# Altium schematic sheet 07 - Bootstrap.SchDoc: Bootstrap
size A3; PageSetup: Record=PageOptions¦CenterHorizontal=True¦CenterVertical=True¦PrintScale=0.70¦XCorrection=1.00¦YCorrection=1.00¦PrintKind=0¦BorderSize=5000000¦LeftOffset=0¦BottomOffset=0¦Orientation=2¦PaperLength=4200¦PaperWidth=2970¦Scale=100¦PaperSource=7¦PrintQuality=600¦MediaType=1¦DitherType=10¦PaperKind=A4¦PrintScaleMode=1; Author: Juan Anzola; SheetNumber: 7; SheetTotal: 21
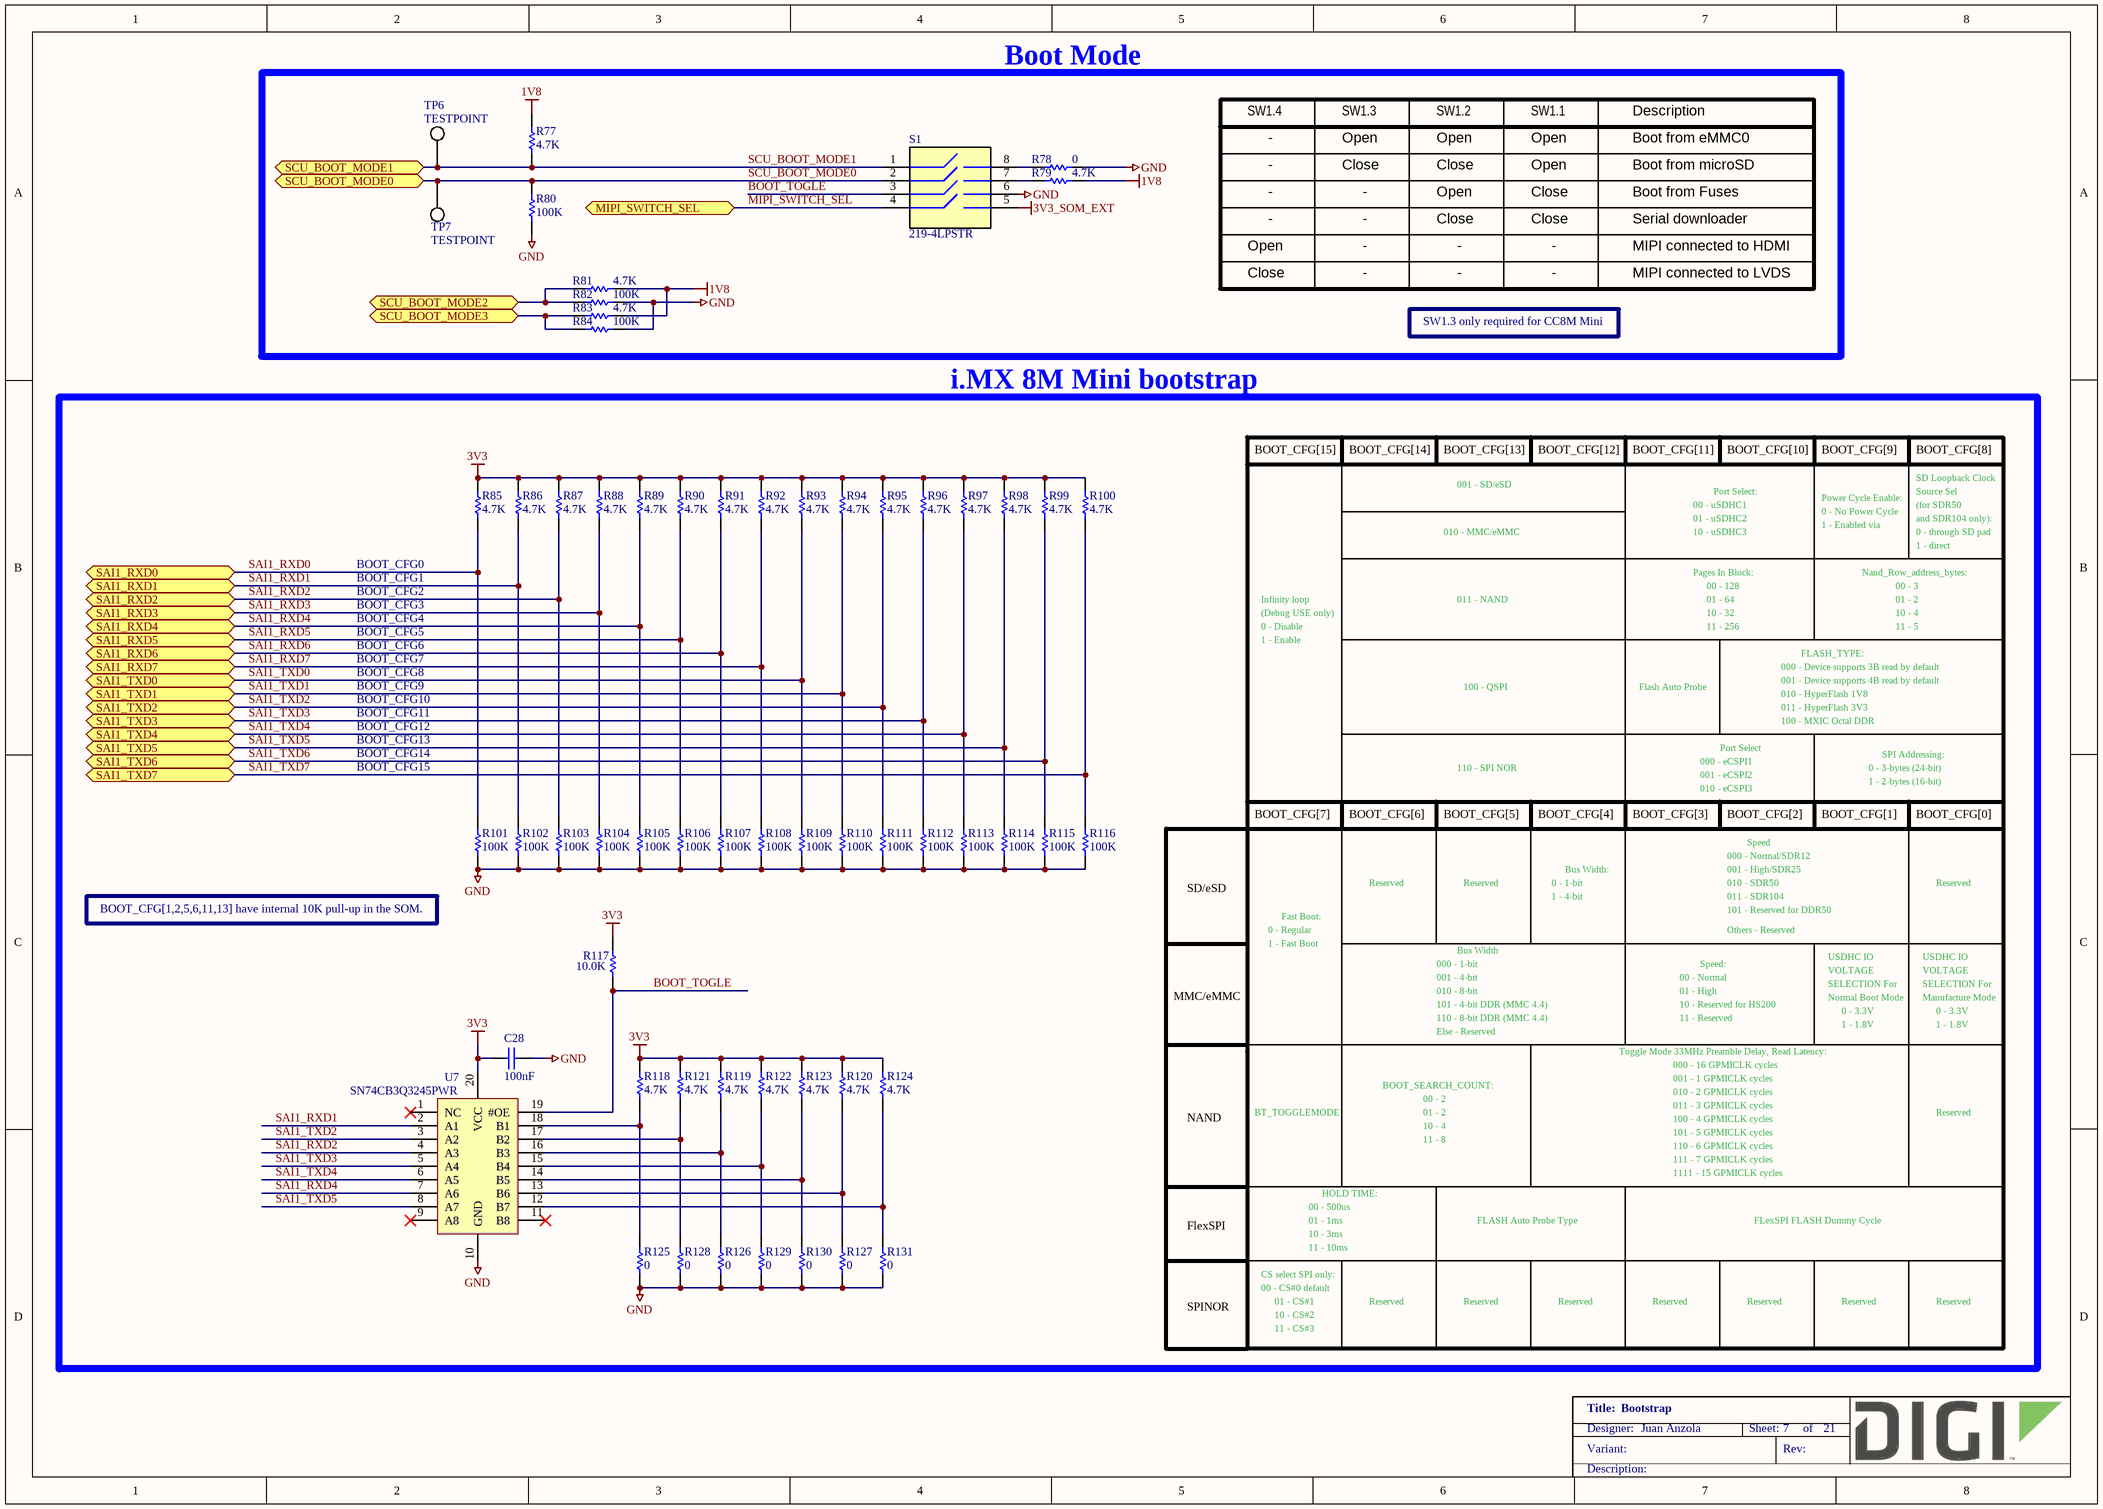
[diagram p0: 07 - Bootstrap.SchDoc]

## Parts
C28  100nF  [CAPC1005X55N]
R77  4.7K  [RESC1005X40N]
R78  0  [RESC1005X40N]
R79  4.7K  [RESC1005X40N]
R80  100K  [RESC1005X40N]
R81  4.7K  [RESC1005X40N]
R82  100K  [RESC1005X40N]
R83  4.7K  [RESC1005X40N]
R84  100K  [RESC1005X40N]
R85  4.7K  [RESC1005X40N]
R86  4.7K  [RESC1005X40N]
R87  4.7K  [RESC1005X40N]
R88  4.7K  [RESC1005X40N]
R89  4.7K  [RESC1005X40N]
R90  4.7K  [RESC1005X40N]
R91  4.7K  [RESC1005X40N]
R92  4.7K  [RESC1005X40N]
R93  4.7K  [RESC1005X40N]
R94  4.7K  [RESC1005X40N]
R95  4.7K  [RESC1005X40N]
R96  4.7K  [RESC1005X40N]
R97  4.7K  [RESC1005X40N]
R98  4.7K  [RESC1005X40N]
R99  4.7K  [RESC1005X40N]
R100  4.7K  [RESC1005X40N]
R101  100K  [RESC1005X40N]
R102  100K  [RESC1005X40N]
R103  100K  [RESC1005X40N]
R104  100K  [RESC1005X40N]
R105  100K  [RESC1005X40N]
R106  100K  [RESC1005X40N]
R107  100K  [RESC1005X40N]
R108  100K  [RESC1005X40N]
R109  100K  [RESC1005X40N]
R110  100K  [RESC1005X40N]
R111  100K  [RESC1005X40N]
R112  100K  [RESC1005X40N]
R113  100K  [RESC1005X40N]
R114  100K  [RESC1005X40N]
R115  100K  [RESC1005X40N]
R116  100K  [RESC1005X40N]
R117  10.0K  [RESC1005X40N]
R118  4.7K  [RESC1005X40N]
R119  4.7K  [RESC1005X40N]
R120  4.7K  [RESC1005X40N]
R121  4.7K  [RESC1005X40N]
R122  4.7K  [RESC1005X40N]
R123  4.7K  [RESC1005X40N]
R124  4.7K  [RESC1005X40N]
R125  0  [RESC1005X40N]
R126  0  [RESC1005X40N]
R127  0  [RESC1005X40N]
R128  0  [RESC1005X40N]
R129  0  [RESC1005X40N]
R130  0  [RESC1005X40N]
R131  0  [RESC1005X40N]
S1  219-4LPSTR  [SOIC254P991X420-8N]
TP6  TESTPOINT  [TP0762]  (no BOM)
TP7  TESTPOINT  [TP0762]  (no BOM)
U7  SN74CB3Q3245PWR  [SOP65P640X120-20N]

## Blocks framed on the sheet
Boot Mode: R77-R84 S1 TP6 TP7
i.MX 8M Mini bootstrap: C28 R85-R131 U7

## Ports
MIPI_SWITCH_SEL (bidir), SAI1_RXD0 (bidir), SAI1_RXD1 (bidir), SAI1_RXD2 (bidir), SAI1_RXD3 (bidir), SAI1_RXD4 (bidir), SAI1_RXD5 (bidir), SAI1_RXD6 (bidir), SAI1_RXD7 (bidir), SAI1_TXD0 (bidir), SAI1_TXD1 (bidir), SAI1_TXD2 (bidir), SAI1_TXD3 (bidir), SAI1_TXD4 (bidir), SAI1_TXD5 (bidir), SAI1_TXD6 (bidir), SAI1_TXD7 (bidir), SCU_BOOT_MODE0 (bidir), SCU_BOOT_MODE1 (bidir), SCU_BOOT_MODE2 (bidir), SCU_BOOT_MODE3 (bidir)

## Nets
1V8: R77.2 R79.2 R81.1 R83.1
3V3: C28.2 R85.1 R86.1 R87.1 R88.1 R89.1 R90.1 R91.1 R92.1 R93.1 R94.1 R95.1 R96.1 R97.1 R98.1 R99.1 R100.1 R117.1 R118.1 R119.1 R120.1 R121.1 R122.1 R123.1 R124.1 U7.20(VCC)
3V3_SOM_EXT: S1.5
GND: C28.1 R78.2 R80.1 R82.1 R84.1 R101.2 R102.2 R103.2 R104.2 R105.2 R106.2 R107.2 R108.2 R109.2 R110.2 R111.2 R112.2 R113.2 R114.2 R115.2 R116.2 R125.1 R126.1 R127.1 R128.1 R129.1 R130.1 R131.1 S1.6 U7.10(GND)
BOOT_TOGLE: R117.2 S1.3 U7.19(#OE)
MIPI_SWITCH_SEL: S1.4 ; port MIPI_SWITCH_SEL
SAI1_RXD0: R85.2 R101.1 ; port SAI1_RXD0
SAI1_RXD1: R86.2 R102.1 U7.2(A1) ; port SAI1_RXD1
SAI1_RXD2: R87.2 R103.1 U7.4(A3) ; port SAI1_RXD2
SAI1_RXD3: R88.2 R104.1 ; port SAI1_RXD3
SAI1_RXD4: R89.2 R105.1 U7.7(A6) ; port SAI1_RXD4
SAI1_RXD5: R90.2 R106.1 ; port SAI1_RXD5
SAI1_RXD6: R91.2 R107.1 ; port SAI1_RXD6
SAI1_RXD7: R92.2 R108.1 ; port SAI1_RXD7
SAI1_TXD0: R93.2 R109.1 ; port SAI1_TXD0
SAI1_TXD1: R94.2 R110.1 ; port SAI1_TXD1
SAI1_TXD2: R95.2 R111.1 U7.3(A2) ; port SAI1_TXD2
SAI1_TXD3: R96.2 R112.1 U7.5(A4) ; port SAI1_TXD3
SAI1_TXD4: R97.2 R113.1 U7.6(A5) ; port SAI1_TXD4
SAI1_TXD5: R98.2 R114.1 U7.8(A7) ; port SAI1_TXD5
SAI1_TXD6: R99.2 R115.1 ; port SAI1_TXD6
SAI1_TXD7: R100.2 R116.1 ; port SAI1_TXD7
SCU_BOOT_MODE0: R80.2 S1.2 TP7.1 ; port SCU_BOOT_MODE0
SCU_BOOT_MODE1: R77.1 S1.1 TP6.1 ; port SCU_BOOT_MODE1
SCU_BOOT_MODE2: R81.2 R82.2 ; port SCU_BOOT_MODE2
SCU_BOOT_MODE3: R83.2 R84.2 ; port SCU_BOOT_MODE3
NetR78_1: R78.1 S1.8
NetR79_1: R79.1 S1.7
NetR118_2: R118.2 R125.2 U7.18(B1)
NetR119_2: R119.2 R126.2 U7.16(B3)
NetR120_2: R120.2 R127.2 U7.13(B6)
NetR121_2: R121.2 R128.2 U7.17(B2)
NetR122_2: R122.2 R129.2 U7.15(B4)
NetR123_2: R123.2 R130.2 U7.14(B5)
NetR124_2: R124.2 R131.2 U7.12(B7)

Not connected (* = marked no-connect by the designer): U7 1(NC)* 9(A8)* 11(B8)*

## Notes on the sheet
- SW1.4
- -
- SW1.3
- Open
- Close
- SW1.2
- SW1.1
- Description
- Boot from eMMC0
- Boot from microSD
- Boot from Fuses
- Serial downloader
- MIPI connected to HDMI
- MIPI connected to LVDS
- SW1.3 only required for CC8M Mini
- BOOT_CFG[15]
- BOOT_CFG[14]
- BOOT_CFG[13]
- BOOT_CFG[12]
- BOOT_CFG[11]
- BOOT_CFG[10]
- BOOT_CFG[9]
- BOOT_CFG[8]
- 001 - SD/eSD
- 00 - uSDHC1
- Port Select:
- Power Cycle Enable:
- 0 - No Power Cycle
- SD Loopback Clock
- Source Sel
- (for SDR50
- BOOT_CFG0
- BOOT_CFG1
- 010 - MMC/eMMC
- 01 - uSDHC2
- 10 - uSDHC3
- Pages In Block:
- 00 - 128
- 1 - Enabled via
- Nand_Row_address_bytes:
- 00 - 3
- and SDR104 only):
- 0 - through SD pad
- 1 - direct
- BOOT_CFG2
- BOOT_CFG3
- BOOT_CFG4
- BOOT_CFG5
- BOOT_CFG6
- Infinity loop
- (Debug USE only)
- 0 - Disable
- 1 - Enable
- 011 - NAND
- 01 - 64
- 10 - 32
- 11 - 256
- 01 - 2
- 11 - 5
- 10 - 4
- BOOT_CFG7
- BOOT_CFG8
- BOOT_CFG9
- BOOT_CFG11
- BOOT_CFG10
- 100 - QSPI
- Flash Auto Probe
- 000 - Device supports 3B read by default
- 001 - Device supports 4B read by default
- 010 - HyperFlash 1V8
- 100 - MXIC Octal DDR
- 011 - HyperFlash 3V3
- FLASH_TYPE:
- BOOT_CFG12
- BOOT_CFG13
- BOOT_CFG14
- BOOT_CFG15
- 110 - SPI NOR
- 000 - eCSPI1
- 001 - eCSPI2
- Port Select
- 0 - 3-bytes (24-bit)
- 1 - 2-bytes (16-bit)
- SPI Addressing:
- BOOT_CFG[7]
- BOOT_CFG[6]
- BOOT_CFG[5]
- BOOT_CFG[4]
- BOOT_CFG[3]
- 010 - eCSPI3
- BOOT_CFG[2]
- 000 - Normal/SDR12
- Speed
- BOOT_CFG[1]
- BOOT_CFG[0]
- BOOT_CFG[1,2,5,6,11,13] have internal 10K pull-up in the SOM.
- SD/eSD
- Fast Boot:
- Reserved
- 0 - 1-bit
- 1 - 4-bit
- Bus Width:
- 001 - High/SDR25
- 010 - SDR50
- 011 - SDR104
- 101 - Reserved for DDR50
- 0 - Regular
- 1 - Fast Boot
- 000 - 1-bit
- 001 - 4-bit
- 010 - 8-bit
- Bus Width
- 00 - Normal
- 01 - High
- Speed:
- Others - Reserved
- USDHC IO
- SELECTION For
- VOLTAGE
- MMC/eMMC
- 101 - 4-bit DDR (MMC 4.4)
- 110 - 8-bit DDR (MMC 4.4)
- Else - Reserved
- Toggle Mode 33MHz Preamble Delay, Read Latency:
- 10 - Reserved for HS200
- 11 - Reserved
- Normal Boot Mode
- 0 - 3.3V
- 1 - 1.8V
- Manufacture Mode
- NAND
- BT_TOGGLEMODE
- BOOT_SEARCH_COUNT:
- 00 - 2
- 000 - 16 GPMICLK cycles
- 001 - 1 GPMICLK cycles
- 010 - 2 GPMICLK cycles
- 011 - 3 GPMICLK cycles
- 100 - 4 GPMICLK cycles
- 11 - 8
- 101 - 5 GPMICLK cycles
- 110 - 6 GPMICLK cycles
- 111 - 7 GPMICLK cycles
- 1111 - 15 GPMICLK cycles
- FlexSPI
- 00 - 500us
- 01 - 1ms
- 10 - 3ms
- 11 - 10ms
- HOLD TIME:
- FLASH Auto Probe Type
- FLexSPI FLASH Dummy Cycle
- SPINOR
- CS select SPI only:
- 00 - CS#0 default
- 01 - CS#1
- 10 - CS#2
- 11 - CS#3

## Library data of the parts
C28 = 1000006: CAP 100nF 16V 10% X7R 0402; Part_Type: Capacitor; Manufacturer: Murata; Manufacturer_Part_Number: GRM155R71C104KA88D; Component_Life_Cycle_State: CAD Reviewed; Area: 0.95; Project: KITT; Tolerance: 10; Digi_PN: 14050552
R77 R79 R81 R83 R85-R100 R118-R124 = 1000038: RES 4.7K OHM 1/10W 5% 0402 SMD; Part_Type: Resistor; Manufacturer: Panasonic - ECG; Manufacturer_Part_Number: ERJ-2GEJ472X; Digi_PN: 13050549; Component_Life_Cycle_State: Proven; Area: 0,95; Project: Adjustable Foundation; Power_WV_SRF: 100; Tolerance: 5
R78 R125-R131 = 1000076: RES 0.0 OHM 1/10W 0402 SMD; Part_Type: Resistor; Manufacturer: Panasonic - ECG; Manufacturer_Part_Number: ERJ-2GE0R00X; Component_Life_Cycle_State: Proven; Area: 0.95; Project: Adjustable Foundation; Power_WV_SRF: 10; Digi_PN: 13050387
R80 R82 R84 R101-R116 = 1000480: RES 100K OHM 1/10W 1% 0402 SMD; Part_Type: Resistor; Manufacturer: Panasonic - ECG; Manufacturer_Part_Number: ERJ-2RKF1003X; Digi_PN: 13051063; Component_Life_Cycle_State: CAD Reviewed; Area: 0,95; Project: KITT; Power_WV_SRF: 100
R117 = 1000537: RES 10.0K OHM 1/10W 1% 0402 SMD; Part_Type: Resistor; Manufacturer: Panasonic - ECG; Manufacturer_Part_Number: ERJ-2RKF1002X; Component_Life_Cycle_State: CAD Reviewed; Area: 0.95; Project: KITT; Power_WV_SRF: 100; Digi_PN: 13051084
S1 = 1002122: SWITCH SLIDE DIP SPST 100MA 20V; Manufacturer: CTS; Digi_PN: 22000318; Component_Life_Cycle_State: Created; Area: 155
TP6 TP7 = CAD0011: TEST POINT 30MIL PAD SMT; Component_Life_Cycle_State: Reviewed; Area: 0,58; Project: CLC
U7 = 1001368: IC SWITCH BUS 8BIT FET 20-TSSOP; Manufacturer: Texas Instruments; Digi_PN: 16052042; Component_Life_Cycle_State: Reviewed; Area: 48,18; Project: ConnectCore i.MX6x SOM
